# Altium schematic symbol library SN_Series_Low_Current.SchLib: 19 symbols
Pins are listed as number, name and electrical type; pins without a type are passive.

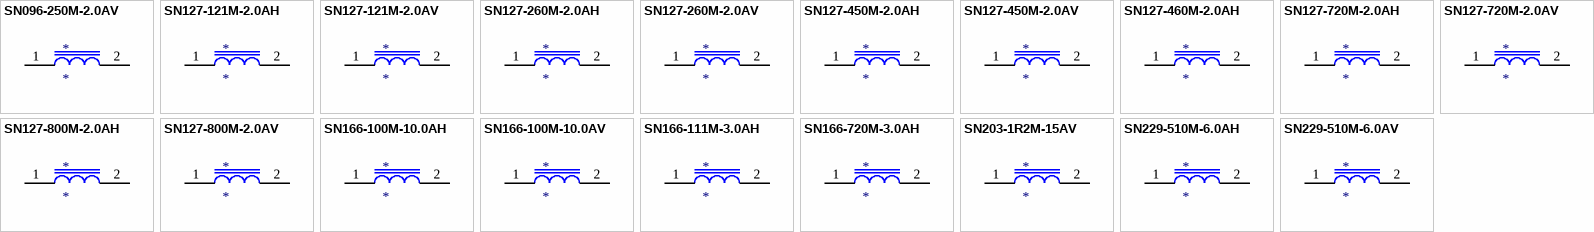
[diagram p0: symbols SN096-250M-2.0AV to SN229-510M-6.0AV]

## SN096-250M-2.0AV
designator *
POWER INDUCTOR 2 A, 25 uH, 35 mOhms, OD 13 mm, HT 7 mm; Manufacturer #1: CWS; Current: 2 A; Inductance: 25 uH
footprint SN096-250M-2.0AV
pins: 1, 2

## SN127-121M-2.0AH
designator *
POWER INDUCTOR 2 A, 120 uH, 60 mOhms, OD 16 mm, HT 11 mm; Manufacturer #1: CWS; Current: 2 A; Inductance: 120 uH
footprint SN127-121M-2.0AH
pins: 1, 2

## SN127-121M-2.0AV
designator *
POWER INDUCTOR 2 A, 120 uH, 60 mOhms, OD 16 mm, HT 11 mm; Manufacturer #1: CWS; Current: 2 A; Inductance: 120 uH
footprint SN127-121M-2.0AV
pins: 1, 2

## SN127-260M-2.0AH
designator *
POWER INDUCTOR 2 A, 26 uH, 23 mOhms, OD 16 mm, HT 8 mm; Manufacturer #1: CWS; Current: 2 A; Inductance: 26 uH
footprint SN127-260M-2.0AH
pins: 1, 2

## SN127-260M-2.0AV
designator *
POWER INDUCTOR 2 A, 26 uH, 23 mOhms, OD 16 mm, HT 8 mm; Manufacturer #1: CWS; Current: 2 A; Inductance: 26 uH
footprint SN127-260M-2.0AV
pins: 1, 2

## SN127-450M-2.0AH
designator *
POWER INDUCTOR 2 A, 45 uH, 37 mOhms, OD 16 mm, HT 8 mm; Manufacturer #1: CWS; Current: 2 A; Inductance: 45 uH
footprint SN127-450M-2.0AH
pins: 1, 2

## SN127-450M-2.0AV
designator *
POWER INDUCTOR 2 A, 45 uH, 37 mOhms, OD 16 mm, HT 8 mm; Manufacturer #1: CWS; Current: 2 A; Inductance: 45 uH
footprint SN127-450M-2.0AV
pins: 1, 2

## SN127-460M-2.0AH
designator *
POWER INDUCTOR 2 A, 46 uH, 38 mOhms, OD 16 mm, HT 8 mm; Manufacturer #1: CWS; Current: 2 A; Inductance: 46 uH
footprint SN127-460M-2.0AH
pins: 1, 2

## SN127-720M-2.0AH
designator *
POWER INDUCTOR 2 A, 72 uH, 50 mOhms, OD 16 mm, HT 9 mm; Manufacturer #1: CWS; Current: 2 A; Inductance: 72 uH
footprint SN127-720M-2.0AH
pins: 1, 2

## SN127-720M-2.0AV
designator *
POWER INDUCTOR 2 A, 72 uH, 50 mOhms, OD 16 mm, HT 9 mm; Manufacturer #1: CWS; Current: 2 A; Inductance: 72 uH
footprint SN127-720M-2.0AV
pins: 1, 2

## SN127-800M-2.0AH
designator *
POWER INDUCTOR 2 A, 80 uH, 53 mOhms, OD 16 mm, HT 11 mm; Manufacturer #1: CWS; Current: 2 A; Inductance: 80 uH
footprint SN127-800M-2.0AH
pins: 1, 2

## SN127-800M-2.0AV
designator *
POWER INDUCTOR 2 A, 80 uH, 53 mOhms, OD 16 mm, HT 11 mm; Manufacturer #1: CWS; Current: 2 A; Inductance: 80 uH
footprint SN127-800M-2.0AV
pins: 1, 2

## SN166-100M-10.0AH
designator *
POWER INDUCTOR 10 A, 10 uH, 10 mOhms, OD 23 mm, HT 11 mm; Manufacturer #1: CWS; Current: 10 A; Inductance: 10 uH
footprint SN166-100M-10.0AH
pins: 1, 2

## SN166-100M-10.0AV
designator *
POWER INDUCTOR 10 A, 10 uH, 10 mOhms, OD 23 mm, HT 11 mm; Manufacturer #1: CWS; Current: 10 A; Inductance: 10 uH
footprint SN166-100M-10.0AV
pins: 1, 2

## SN166-111M-3.0AH
designator *
POWER INDUCTOR 3 A, 110 uH, 36 mOhms, OD 21 mm, HT 12 mm; Manufacturer #1: CWS; Current: 3 A; Inductance: 110 uH
footprint SN166-111M-3.0AH
pins: 1, 2

## SN166-720M-3.0AH
designator *
POWER INDUCTOR 3 A, 72 uH, 64 mOhms, OD 21 mm, HT 11 mm; Manufacturer #1: CWS; Current: 3 A; Inductance: 72 uH
footprint SN166-720M-3.0AH
pins: 1, 2

## SN203-1R2M-15AV
designator *
POWER INDUCTOR 15 A, 1.2 uH, 1.3 mOhms, OD 27 mm, HT 12 mm; Manufacturer #1: CWS; Current: 15 A; Inductance: 1.2 uH
footprint SN203-1R2M-15AV
pins: 1, 2

## SN229-510M-6.0AH
designator *
POWER INDUCTOR 6 A, 51 uH, 16 mOhms, OD 30 mm, HT 17 mm; Manufacturer #1: CWS; Current: 6 A; Inductance: 51 uH
footprint SN229-510M-6.0AH
pins: 1, 2

## SN229-510M-6.0AV
designator *
POWER INDUCTOR 6 A, 51 uH, 16 mOhms, OD 30 mm, HT 17 mm; Manufacturer #1: CWS; Current: 6 A; Inductance: 51 uH
footprint SN229-510M-6.0AV
pins: 1, 2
